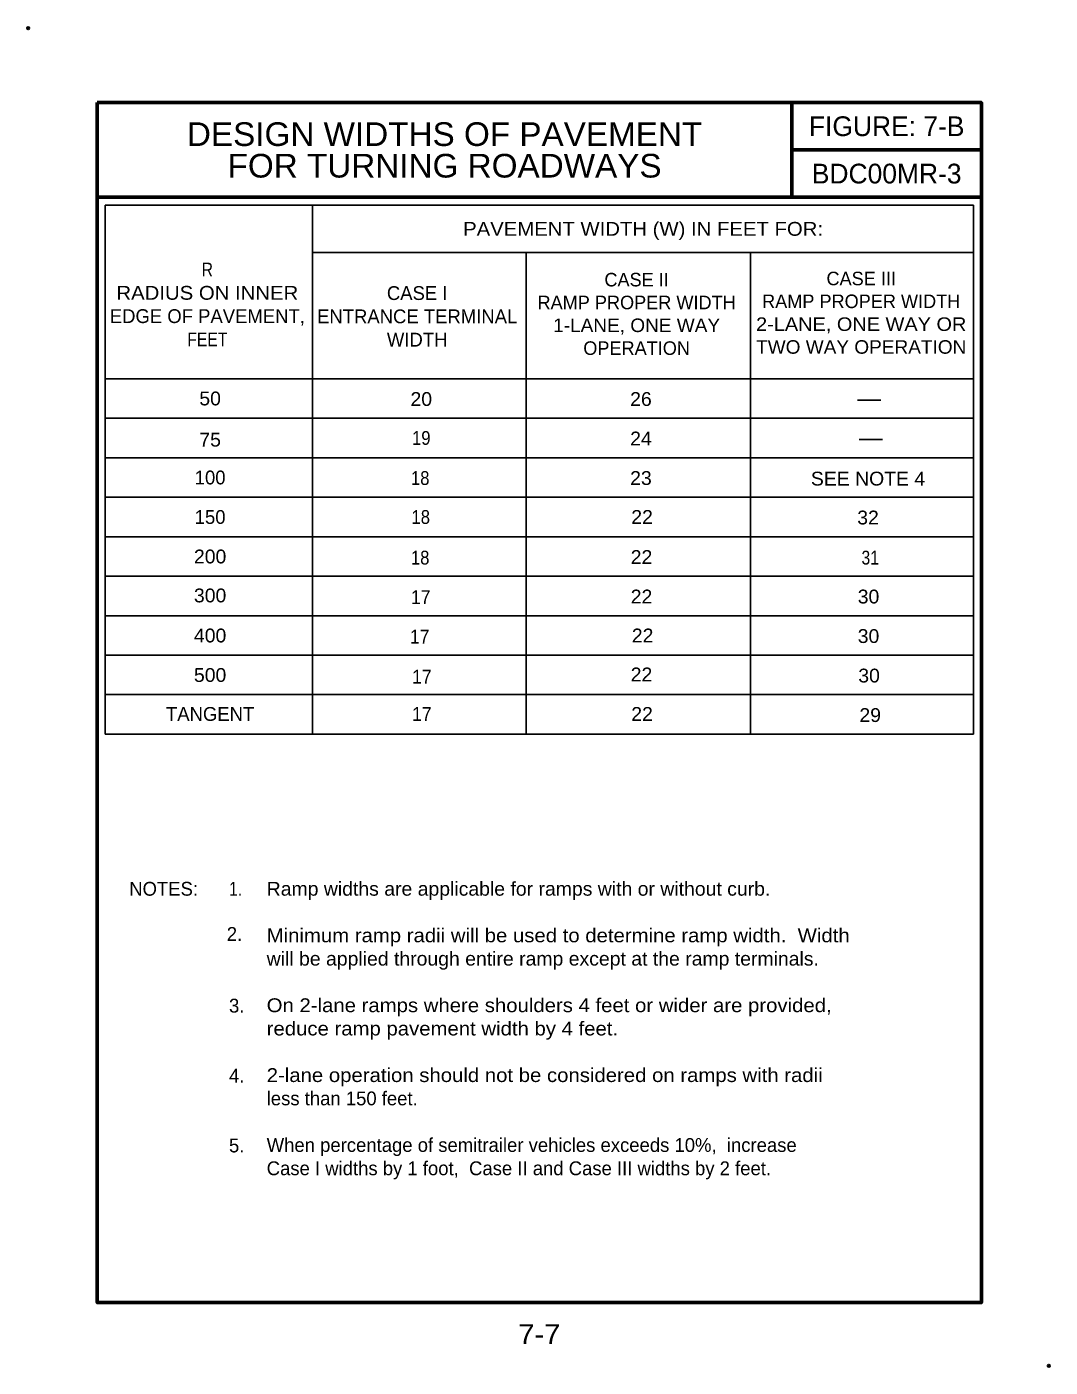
# Model space of a CAD drawing. Extents: x -6.663 to -5.988, y 1.869 to 2.753.
import ezdxf
from ezdxf.enums import TextEntityAlignment as Align

# ---------------------------------------------------------------- set-up
doc = ezdxf.new("R2010")
doc.units = 0
doc.header["$LTSCALE"] = 0.0036
doc.header["$PDMODE"] = 32
doc.header["$PDSIZE"] = 0.0018
doc.layers.add('1', color=7, linetype='Continuous', lineweight=25)

msp = doc.modelspace()

# ---------------------------------------------------------------- linework, layer by layer
at = {"layer": '1', "lineweight": 53}
for p, q in [((-6.158583, 2.702842), (-6.158583, 2.640342)), ((-6.158583, 2.671592), (-6.033583, 2.671592)), ((-6.616917, 2.640342), (-6.033583, 2.640342))]:
    msp.add_line(p, q, dxfattribs=at)
at = {"layer": '1'}
for p, q in [((-6.611708, 2.635133), (-6.038792, 2.635133)), ((-6.611708, 2.635133), (-6.611708, 2.286175)), ((-6.474808, 2.635133), (-6.474808, 2.286175)), ((-6.038792, 2.635133), (-6.038792, 2.286175)), ((-6.474808, 2.603883), (-6.038792, 2.603883)), ((-6.334033, 2.603883), (-6.334033, 2.286175)), ((-6.185975, 2.603883), (-6.185975, 2.286175)), ((-6.611708, 2.52055), (-6.038792, 2.52055)), ((-6.611708, 2.52055), (-6.038792, 2.52055)), ((-6.115442, 2.506492), (-6.099983, 2.506492)), ((-6.611708, 2.494508), (-6.038792, 2.494508)), ((-6.114342, 2.480425), (-6.098883, 2.480425)), ((-6.611708, 2.468467), (-6.038792, 2.468467)), ((-6.611708, 2.442425), (-6.038792, 2.442425)), ((-6.611708, 2.416383), (-6.038792, 2.416383)), ((-6.611708, 2.390342), (-6.038792, 2.390342)), ((-6.611708, 2.3643), (-6.038792, 2.3643)), ((-6.611708, 2.338258), (-6.038792, 2.338258)), ((-6.611708, 2.312217), (-6.038792, 2.312217)), ((-6.611708, 2.286175), (-6.038792, 2.286175))]:
    msp.add_line(p, q, dxfattribs=at)
at = {"layer": '1', "lineweight": 53}
msp.add_lwpolyline([(-6.616917, 2.702842), (-6.033583, 2.702842), (-6.033583, 1.911175), (-6.616917, 1.911175)], close=True, dxfattribs=at)
at = {"layer": '1'}
for p in [(-6.662458, 2.7519), (-5.989125, 1.8694)]:
    msp.add_point(p, dxfattribs=at)

# ---------------------------------------------------------------- texts
for s, height, width, p in [('DESIGN WIDTHS OF PAVEMENT', 0.01562, 1.05, (-6.387754, 2.674192)), ('FOR TURNING ROADWAYS', 0.01562, 1.05, (-6.387746, 2.653358)), ('PAVEMENT WIDTH (W) IN FEET FOR:', 0.009108, 1.1, (-6.2568, 2.61495)), ('R', 0.009117, 0.85, (-6.544254, 2.5881)), ('RADIUS ON INNER', 0.009117, 1.1, (-6.544254, 2.572733)), ('1-LANE, ONE WAY', 0.008934, 1.05, (-6.261058, 2.551417)), ('2-LANE, ONE WAY OR', 0.008934, 1.1, (-6.1129, 2.552175)), ('FEET', 0.009117, 0.85, (-6.544254, 2.542)), ('TWO WAY OPERATION', 0.008934, 1.05, (-6.112896, 2.537117)), ('50', 0.009117, 1.05, (-6.542425, 2.503042)), ('20', 0.009117, 1.05, (-6.403117, 2.502675)), ('26', 0.009117, 1.05, (-6.258204, 2.502675)), ('75', 0.009117, 1.05, (-6.542421, 2.475875)), ('19', 0.009117, 0.9, (-6.403117, 2.476983)), ('24', 0.009117, 1.05, (-6.258204, 2.476617)), ('18', 0.009117, 0.9, (-6.403821, 2.45055)), ('23', 0.009117, 1.05, (-6.2582, 2.45055)), ('SEE NOTE 4', 0.009117, 1.05, (-6.1084, 2.450175)), ('18', 0.009117, 0.9, (-6.403463, 2.424858)), ('22', 0.009117, 1.05, (-6.257467, 2.424858)), ('32', 0.009117, 1.05, (-6.1084, 2.424492)), ('200', 0.009117, 1.05, (-6.542421, 2.398792)), ('18', 0.009117, 0.9, (-6.403846, 2.39805)), ('22', 0.009117, 1.05, (-6.257833, 2.398425)), ('31', 0.009117, 0.85, (-6.106954, 2.39805)), ('300', 0.009117, 1.05, (-6.542421, 2.373092)), ('17', 0.009117, 0.95, (-6.403471, 2.371992)), ('22', 0.009117, 1.05, (-6.257833, 2.372367)), ('30', 0.009117, 1.05, (-6.108075, 2.372367)), ('400', 0.009117, 1.05, (-6.542421, 2.346667)), ('17', 0.009117, 0.95, (-6.404187, 2.345925)), ('22', 0.009117, 1.05, (-6.257108, 2.346667)), ('30', 0.009117, 1.05, (-6.108075, 2.346292)), ('500', 0.009117, 1.05, (-6.542421, 2.320608)), ('17', 0.009117, 0.95, (-6.402729, 2.3195)), ('22', 0.009117, 1.05, (-6.257842, 2.320967)), ('30', 0.009117, 1.05, (-6.107708, 2.320233)), ('17', 0.009117, 0.95, (-6.402738, 2.294908)), ('22', 0.009117, 1.05, (-6.257467, 2.294908)), ('29', 0.009117, 1.05, (-6.106967, 2.294167)), ('7-7', 0.01303, 1.1, (-6.32525, 1.883775))]:
    msp.add_text(s, height=height, dxfattribs=dict(at, width=width)).set_placement(p, align=Align.CENTER)
for s, height, p in [('FIGURE: 7-B', 0.01303, (-6.096083, 2.6807)), ('BDC00MR-3', 0.01303, (-6.096088, 2.64945)), ('CASE III', 0.008934, (-6.1129, 2.582292)), ('CASE II', 0.008934, (-6.261058, 2.581533)), ('CASE I', 0.009117, (-6.405833, 2.572575)), ('RAMP PROPER WIDTH', 0.008934, (-6.261058, 2.566475)), ('RAMP PROPER WIDTH', 0.008934, (-6.1129, 2.567233)), ('EDGE OF PAVEMENT,', 0.009117, (-6.544254, 2.557367)), ('ENTRANCE TERMINAL', 0.009117, (-6.405838, 2.557208)), ('WIDTH', 0.009117, (-6.405838, 2.541842)), ('OPERATION', 0.008934, (-6.261063, 2.536358)), ('100', 0.009117, (-6.542421, 2.450917)), ('150', 0.009117, (-6.542421, 2.424858)), ('TANGENT', 0.009117, (-6.542421, 2.294908))]:
    msp.add_text(s, height=height, dxfattribs=at).set_placement(p, align=Align.CENTER)
for s, p in [('NOTES:', (-6.595792, 2.179567)), ('2.', (-6.531433, 2.149758)), ('3.', (-6.529958, 2.10245)), ('4.', (-6.529958, 2.056242)), ('less than 150 feet.', (-6.5051, 2.041267)), ('5.', (-6.529983, 2.010225)), ('When percentage of semitrailer vehicles exceeds 10%,  increase', (-6.5051, 2.010533)), ('Case I widths by 1 foot,  Case II and Case III widths by 2 feet.', (-6.5051, 1.995167))]:
    msp.add_text(s, height=0.009117, dxfattribs=at).set_placement(p)
for s, width, p in [('1.', 0.85, (-6.529958, 2.179567)), ('Ramp widths are applicable for ramps with or without curb.', 1.05, (-6.5051, 2.179567)), ('Minimum ramp radii will be used to determine ramp width.  Width', 1.1, (-6.5051, 2.148833)), ('will be applied through entire ramp except at the ramp terminals.', 1.05, (-6.5051, 2.133467)), ('On 2-lane ramps where shoulders 4 feet or wider are provided,', 1.1, (-6.5051, 2.102733)), ('reduce ramp pavement width by 4 feet.', 1.1, (-6.5051, 2.087367)), ('2-lane operation should not be considered on ramps with radii', 1.1, (-6.5051, 2.056633))]:
    msp.add_text(s, height=0.009117, dxfattribs=dict(at, width=width)).set_placement(p)

doc.saveas('drawing.dxf')
